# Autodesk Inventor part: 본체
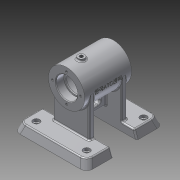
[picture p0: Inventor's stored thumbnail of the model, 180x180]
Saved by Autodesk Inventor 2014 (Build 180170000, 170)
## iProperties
Created: 2016-07
Part Number: 본체
Material: 알루미늄 6061
Document SubType Name: Modeling
Designer: basic
Density: 2.71 g/cm^3
Appearance: 알루미늄 - 평지
Mass: 547.948 g
Surface Area: 574.579 cm^2
Volume: 202.195 cm^3
Author: basic
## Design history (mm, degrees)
sketch "스케치1"
  geometry: L1 (35, 70)-(-35, 70); L2 (35, 70)-(35, 97); L3 (35, 97)-(-35, 97); L4 (-35, 97)-(-35, 70); 2 further points
  constraints: 8 end point, 1 horizontal, 1 midpoint, 1 parallel, 1 perpendicular, 1 vertical, 1 vertical alignment
  dimensions: "d0" = 70 distance of L1.start L1.end; "d1" = 70 distance from line of L1 point (0, 0); "d2" = 54 diameter of L3 L1
revolve "회전1" sketch "스케치1" stored, may be unused: angle "d3" = 90 deg
sketch "스케치2"
  geometry: L1 (-49, 0)-(49, 0) reference; L2 (35, 43)-(35, 97) reference; L3 (-35, 43)-(-35, 97) reference; L4 (35, 70)-(-35, 70); L5 (35, 70)-(35, 86); L6 (35, 86)-(23, 86); L7 (23, 86)-(23, 84); L8 (23, 84)-(21, 84); L9 (21, 84)-(21, 92); L10 (21, 92)-(-21, 92); L11 (-21, 92)-(-21, 84); L12 (-21, 84)-(-23, 84); L13 (-23, 84)-(-23, 86); L14 (-23, 86)-(-35, 86); L15 (-35, 70)-(-35, 86); 5 further points
  constraints: 24 end point, 6 midpoint, 6 parallel, 3 collinear, 3 perpendicular, 2 horizontal alignment, 2 point on line
  dimensions: "d4" = 32 diameter of L6 L4; "d5" = 28 diameter of L8 L4; "d6" = 44 diameter of L10 L4; "d7" = 42 distance of L9.end L10.end; "d8" = 12 distance of L5.end L6.end
revolve "회전2" sketch "스케치2" stored, may be unused: angle "d9" = 90 deg
sketch "스케치3"
  geometry: L1 (-20, -50)-(-55, -50); L2 (-55, -50)-(-55, 50); L3 (-55, 50)-(-20, 50); L4 (-20, 50)-(-20, -50); L5 (-20, -50)-(-55, 50); L6 (-55, -50)-(-20, 50); L7 (55, -50)-(20, -50); L8 (20, -50)-(20, 50); L9 (20, 50)-(55, 50); L10 (55, 50)-(55, -50); L11 (55, -50)-(20, 50); L12 (20, -50)-(55, 50); 8 further points
  constraints: 24 end point, 9 midpoint, 4 parallel, 3 horizontal alignment, 2 horizontal, 2 perpendicular, 1 collinear
  dimensions: "d10" = 100 distance of L1.end L2.end; "d11" = 110 distance between parallel lines of L10 L2; "d12" = 35 distance of L1.start L1.end; "d13" = 55 distance from line of L2 point (0, 0)
extrude "돌출1" join sketch "스케치3" distance "d14" = 12; taper "d15" = 0 deg
sketch "스케치4"
  geometry: L1 (-20, -50)-(-20, 50) reference; L2 (-20, -27)-(-28, -27); L3 (-28, -27)-(-28, 27); L4 (-28, 27)-(-20, 27); L5 (-20, 27)-(-20, -27); L6 (-20, -27)-(-28, 27); L7 (-28, -27)-(-20, 27); 3 further points
  constraints: 12 end point, 4 midpoint, 2 parallel, 1 horizontal, 1 perpendicular
  dimensions: "d16" = 8 distance of L2.start L2.end; "d17" = 54 distance of L2.end L3.end
extrude "돌출2" join sketch "스케치4" stored distance "d18" = 12; taper "d19" = 0 deg
node "작업 평면1"
sketch "스케치6"
  geometry: L1 (24.368, -4)-(-24.368, -4); L2 (-24.368, -4)-(-24.368, 4); L3 (-24.368, 4)-(24.368, 4); L4 (24.368, 4)-(24.368, -4); L5 (24.368, -4)-(-24.368, 4); L6 (-24.368, -4)-(24.368, 4); L7 (-20, 50)-(-20, -50) reference; L8 (20, -50)-(20, 50) reference; 7 further points; 1 other entity
  constraints: 12 end point, 5 midpoint, 2 parallel, 1 coincident, 1 horizontal, 1 perpendicular, 2 other
  dimensions: "d24" = 8 distance of L3.end L1.start
extrude "돌출4" join sketch "스케치6" stored distance "d25" = 8; taper "d26" = 0 deg
sketch "스케치7"
  geometry: L1 (0, 21.298)-(40, 21.298) reference; L2 (0, 0)-(0, 21.298) reference; L3 (12, 10.649)-(28, 10.649); L4 (12, 7.149)-(28, 7.149); L5 (28, 14.149)-(12, 14.149); A1 r 3.5 centre (12, 10.649) between (12, 14.149) and (12, 7.149); A2 r 3.5 centre (28, 10.649) between (28, 7.149) and (28, 14.149); 4 further points
  constraints: 8 end point, 4 point on circle, 4 tangent, 3 midpoint, 2 centre point, 2 parallel, 1 horizontal alignment, 1 vertical alignment
  dimensions: "d27" = 3.5 radius of A2; "d170" = 23 dimension on A1 A2
extrude "돌출5" cut sketch "스케치7" stored distance "d29" = 8; taper "d30" = 0 deg
node "작업 평면2"
sketch "스케치8"
  geometry: L1 (-35, 27)-(-35, -27) reference; C1 r 5 at (-13, 0); 1 further point
  constraints: 1 centre point, 1 horizontal alignment
  dimensions: "d32" = 22 distance from line of L1 C1.centre; "d33" = 10 diameter of C1
extrude "돌출6" join sketch "스케치8" stored distance "d34" = 8; taper "d35" = 0 deg
sketch "스케치9" dims "d46" = 42
  geometry: C1 r 16 at (0, 0) reference; C2 r 27 at (0, 0) reference; 3 further points
  constraints: 2 horizontal alignment, 1 coincident, 2 other
hole "구멍2" sketch "스케치9" at (-21, 0) diameter "d47" = 3.242; stored, may be unused: countersink angle "d51" = 90 deg, drill point angle "d53" = 118 deg; dims "d48" = 8, "d49" = 4, "d50" = 2, "d52" = 10
sketch "스케치10"
  geometry: L1 (0, 70)-(0, 43); L2 (0, 70)-(15.898, 44.559); L3 (15.898, 44.559)-(20.986, 47.738); L4 (20.986, 47.738)-(16.747, 54.522); L5 (16.747, 54.522)-(11.658, 51.343); C1 r 22 at (0, 70) reference; 1 further point
  constraints: 10 end point, 3 perpendicular, 1 point on line, 1 tangent, 1 vertical, 1 vertical alignment, 1 other
  dimensions: "d59" = 32 deg angle of L1 L2; "d60" = 30 distance of L1.start L2.end; "d62" = 12 diameter of L4 L2
revolve "회전3" sketch "스케치10" stored, may be unused: angle "d63" = 90 deg
sketch "스케치12"
  geometry: L1 (-42.5, 37.5)-(-42.5, -37.5); L2 (-55, -50)-(-55, 50) reference; 2 further points
  constraints: 2 end point, 1 horizontal alignment, 1 midpoint, 1 vertical
  dimensions: "d91" = 75 distance of L1.start L1.end; "d93" = 12.5 distance between parallel lines of L2 L1
hole "구멍4" sketch "스케치12" at (-42.5, -37.5), (-42.5, 37.5) diameter "d94" = 6; stored, may be unused: countersink angle "d98" = 90 deg, drill point angle "d100" = 0 deg; dims "d95" = 8, "d96" = 10, "d97" = 4, "d99" = 10
fillet "모깎기4" dims "d102" = 2
fillet "모깎기5" dims "d103" = 2
fillet "모깎기7" dims "d105" = 2
fillet "모깎기9" dims "d107" = 2
fillet "모깎기11" dims "d109" = 2
fillet "모깎기13" dims "d111" = 0.3
fillet "모깎기14" dims "d112" = 3
chamfer "모따기1" distance "d113" = 1; stored, may be unused: second distance "d114" = 2, angle "d115" = 45 deg
node "작업 평면3"
sketch "스케치13"
  geometry: L1 (35, 97)-(-35, 97) reference; L2 (-35, 97)-(-35, 43) reference; 2 further points
  constraints: 1 other
  dimensions: "d117" = 35 distance from line of L2 point (0, 70); "d118" = 27 distance from line of L1 point (0, 70)
feature "엠보싱1" sketch "스케치13" dims "d4" = 32, "d5" = 28, "d6" = 44, "d7" = 42, "d8" = 12, "d119" = 0.5, "d120" = 0
hole "구멍5" diameter "d144" = 5.188; stored, may be unused: countersink angle "d148" = 90 deg, drill point angle "d150" = 0 deg; dims "d142" = 10, "d143" = 10, "d145" = 8, "d146" = 10, "d147" = 4, "d149" = 10
hole "구멍6" diameter "d153" = 5.188; stored, may be unused: countersink angle "d157" = 90 deg, drill point angle "d159" = 0 deg; dims "d151" = 10, "d152" = 10, "d154" = 8, "d155" = 10, "d156" = 4, "d158" = 10
fillet "모깎기22" dims "d160" = 2
fillet "모깎기23" dims "d161" = 2
feature "면 기울기20" dims angle "d162" = 20 deg
feature "면 기울기21" dims angle "d163" = 20 deg
feature "면 기울기22" dims angle "d164" = 20 deg
feature "면 기울기23" dims angle "d165" = 20 deg
feature "면 기울기24" dims angle "d166" = 20 deg
feature "면 기울기25" dims angle "d167" = 20 deg
fillet "모깎기24" dims "d168" = 10
fillet "모깎기25" dims "d169" = 2
node "솔리드1"
mirror "대칭1"
pattern_circular "원형 패턴1" dims angle "d55" = 360 deg
mirror "대칭2"
mirror "대칭3"
node "투영된 루프1"
other parameters: "d23" = 22, "d116" = -27
